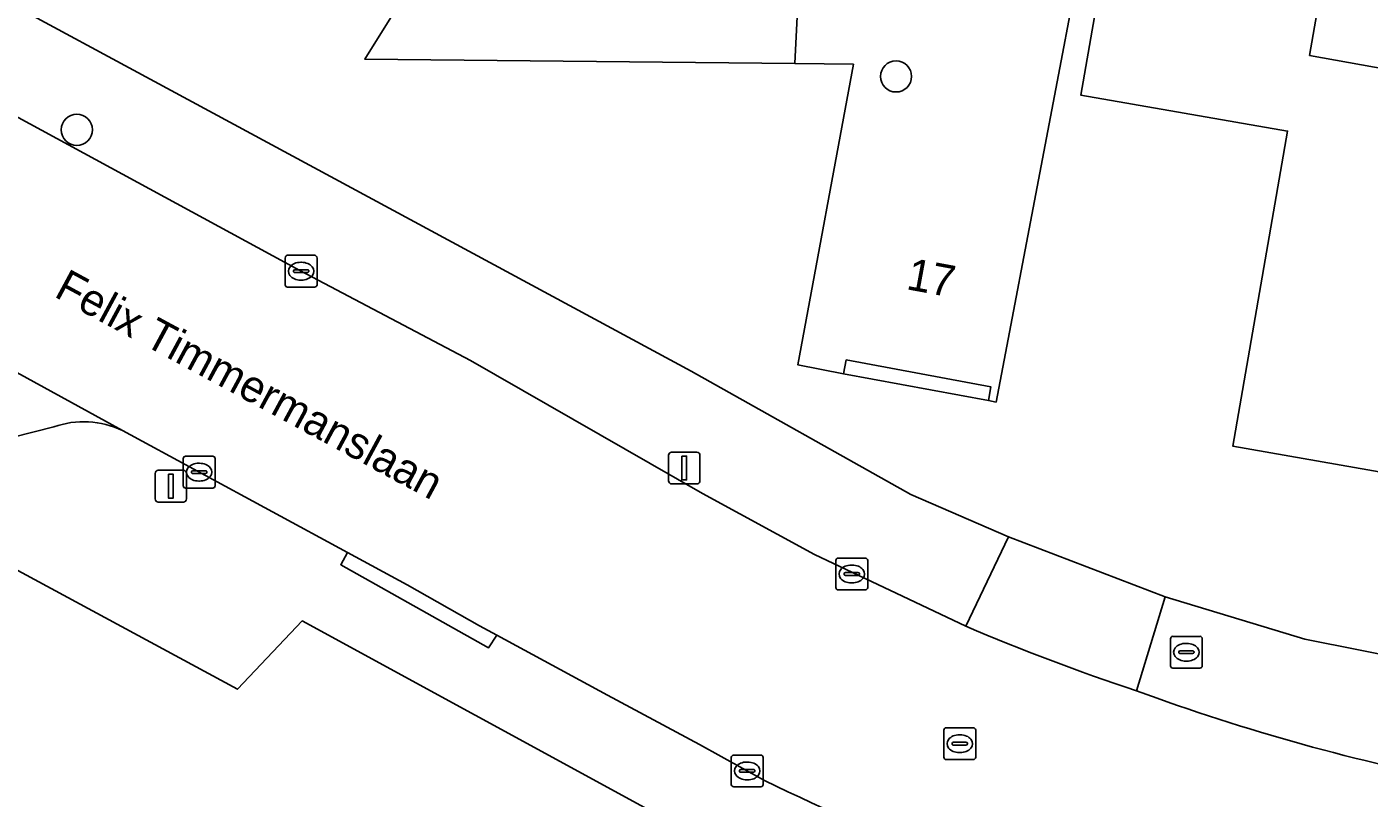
# Model space of a CAD drawing. Extents: x 161258 to 161838, y 380833 to 381727.
# Drawn here: x 161655.94 to 161698.14, y 381051.29 to 381075.53 of the extents above; entities that cross this region are included whole.
import ezdxf

# ---------------------------------------------------------------- set-up
doc = ezdxf.new("R2010")
doc.units = 0
for name, color, linetype in [('IMGEO_Boom', 7, 'Continuous'), ('IMGEO_Brandkraan', 7, 'Continuous'), ('IMGEO_Erf', 7, 'Continuous'), ('IMGEO_Kolk', 7, 'Continuous'), ('IMGEO_Lichtmast', 7, 'Continuous'), ('IMGEO_Muur', 7, 'Continuous'), ('IMGEO_Openbare_ruimte_label', 7, 'Continuous'), ('IMGEO_Pand', 7, 'Continuous'), ('IMGEO_Pand_nummerreeks', 7, 'Continuous'), ('IMGEO_Pand_overbouw', 7, 'Continuous'), ('IMGEO_Parkeervlak_open', 7, 'Continuous'), ('IMGEO_Rijbaan_lokaal_open', 7, 'Continuous'), ('IMGEO_Rioolput', 7, 'Continuous'), ('IMGEO_Voetpad_open', 7, 'Continuous')]:
    doc.layers.add(name, color=color, linetype=linetype)

msp = doc.modelspace()

# ---------------------------------------------------------------- linework, layer by layer
at = {"layer": 'IMGEO_Boom'}
for centre in [(161683.262, 381073.968), (161657.506, 381072.291)]:
    msp.add_circle(centre, 0.489, dxfattribs=at)
at = {"layer": 'IMGEO_Brandkraan'}
for p, q in [((161691.891, 381055.445), (161691.891, 381056.297)), ((161691.966, 381056.371), (161692.818, 381056.371)), ((161692.892, 381056.297), (161692.892, 381055.445)), ((161692.15, 381055.865), (161692.15, 381055.877)), ((161692.193, 381055.914), (161692.591, 381055.914)), ((161692.379, 381056.151), (161692.404, 381056.151)), ((161692.634, 381055.877), (161692.634, 381055.865)), ((161692.588, 381055.828), (161692.19, 381055.828)), ((161692.402, 381055.591), (161692.377, 381055.591)), ((161692.818, 381055.371), (161691.966, 381055.371))]:
    msp.add_line(p, q, dxfattribs=at)
for points in [[(161691.891, 381055.445), (161691.891, 381056.297)], [(161691.966, 381056.371), (161692.818, 381056.371)], [(161692.892, 381056.297), (161692.892, 381055.445)], [(161692.818, 381055.371), (161691.966, 381055.371)]]:
    msp.add_lwpolyline(points, dxfattribs=at)
for centre, radius, start, end in [((161691.968, 381056.295), 0.0765, 91.552, 178.448), ((161691.968, 381056.295), 0.0765, 91.552, 178.448), ((161692.816, 381056.295), 0.0765, 1.552, 88.448), ((161692.816, 381056.295), 0.0765, 1.552, 88.448), ((161692.19, 381055.874), 0.0403, 85.8775, 175.7526), ((161692.595, 381055.876), 0.0386, 1.7309, 96.639), ((161692.187, 381055.864), 0.0366, 178.938, 274.7102), ((161692.591, 381055.871), 0.043, 264.8664, 352.4533), ((161691.968, 381055.447), 0.0765, 181.552, 268.448), ((161691.968, 381055.447), 0.0765, 181.552, 268.448), ((161692.816, 381055.447), 0.0765, 271.552, 358.448), ((161692.816, 381055.447), 0.0765, 271.552, 358.448)]:
    msp.add_arc(centre, radius, start, end, dxfattribs=at)
for centre, major_axis, ratio, start_param, end_param in [((161692.378, 381055.871), (-0.387, 0.002), 0.722429, 4.712389, 7.853982), ((161692.403, 381055.871), (-0.39, 0.002), 0.717154, 1.570796, 4.712389)]:
    msp.add_ellipse(centre, major_axis=major_axis, ratio=ratio, start_param=start_param, end_param=end_param, dxfattribs=at)
at = {"layer": 'IMGEO_Erf'}
for points in [[(161599.292, 381107.15), (161603.367, 381104.463), (161608.252, 381101.703), (161676.825, 381064.703), (161683.729, 381060.833), (161686.794, 381059.495), (161691.724, 381057.608), (161696.114, 381056.287), (161709.767, 381053.57)], [(161689.325, 381079.031), (161686.406, 381063.731), (161686.171, 381063.778), (161686.239, 381064.217), (161681.697, 381065.06), (161681.611, 381064.618), (161680.177, 381064.899), (161681.925, 381074.353), (161680.083, 381074.372), (161680.401, 381080.903)], [(161696.768, 381077.515), (161696.265, 381074.626), (161709.453, 381072.261), (161709.255, 381071.129), (161707.307, 381059.995), (161699.889, 381061.293), (161693.85, 381062.349), (161695.574, 381072.251), (161689.072, 381073.384), (161689.93, 381078.31)], [(161675.471, 381050.931), (161664.588, 381056.855), (161662.556, 381054.709), (161631.294, 381071.59)]]:
    msp.add_lwpolyline(points, dxfattribs=at)
at = {"layer": 'IMGEO_Kolk'}
for p, q in [((161664.057, 381067.42), (161664.057, 381068.272)), ((161664.132, 381068.346), (161664.984, 381068.346)), ((161664.545, 381068.126), (161664.57, 381068.126)), ((161665.058, 381068.272), (161665.058, 381067.42)), ((161664.316, 381067.84), (161664.316, 381067.852)), ((161664.754, 381067.803), (161664.356, 381067.803)), ((161664.359, 381067.889), (161664.757, 381067.889)), ((161664.8, 381067.852), (161664.8, 381067.84)), ((161664.984, 381067.346), (161664.132, 381067.346)), ((161664.568, 381067.566), (161664.543, 381067.566)), ((161660.852, 381061.105), (161660.852, 381061.957)), ((161660.927, 381062.031), (161661.779, 381062.031)), ((161661.34, 381061.811), (161661.365, 381061.811)), ((161661.853, 381061.957), (161661.853, 381061.105)), ((161661.111, 381061.525), (161661.111, 381061.537)), ((161661.549, 381061.488), (161661.151, 381061.488)), ((161661.154, 381061.574), (161661.552, 381061.574)), ((161661.595, 381061.537), (161661.595, 381061.525)), ((161661.779, 381061.031), (161660.927, 381061.031)), ((161661.363, 381061.251), (161661.338, 381061.251)), ((161681.445, 381058.83), (161682.297, 381058.83)), ((161681.37, 381057.904), (161681.37, 381058.756)), ((161681.858, 381058.61), (161681.883, 381058.61)), ((161682.371, 381058.756), (161682.371, 381057.904)), ((161681.629, 381058.324), (161681.629, 381058.336)), ((161682.067, 381058.287), (161681.669, 381058.287)), ((161681.672, 381058.373), (161682.07, 381058.373)), ((161681.881, 381058.05), (161681.856, 381058.05)), ((161682.113, 381058.336), (161682.113, 381058.324)), ((161682.297, 381057.83), (161681.445, 381057.83)), ((161678.083, 381051.715), (161678.083, 381052.567)), ((161678.158, 381052.641), (161679.01, 381052.641)), ((161679.084, 381052.567), (161679.084, 381051.715)), ((161678.342, 381052.135), (161678.342, 381052.147)), ((161678.78, 381052.098), (161678.382, 381052.098)), ((161678.385, 381052.184), (161678.783, 381052.184)), ((161678.571, 381052.421), (161678.596, 381052.421)), ((161678.826, 381052.147), (161678.826, 381052.135)), ((161678.594, 381051.861), (161678.569, 381051.861)), ((161679.01, 381051.641), (161678.158, 381051.641))]:
    msp.add_line(p, q, dxfattribs=at)
for points in [[(161664.057, 381067.42), (161664.057, 381068.272)], [(161664.132, 381068.346), (161664.984, 381068.346)], [(161665.058, 381068.272), (161665.058, 381067.42)], [(161664.984, 381067.346), (161664.132, 381067.346)], [(161660.852, 381061.105), (161660.852, 381061.957)], [(161660.927, 381062.031), (161661.779, 381062.031)], [(161661.853, 381061.957), (161661.853, 381061.105)], [(161661.779, 381061.031), (161660.927, 381061.031)], [(161681.445, 381058.83), (161682.297, 381058.83)], [(161681.37, 381057.904), (161681.37, 381058.756)], [(161682.371, 381058.756), (161682.371, 381057.904)], [(161682.297, 381057.83), (161681.445, 381057.83)], [(161678.083, 381051.715), (161678.083, 381052.567)], [(161678.158, 381052.641), (161679.01, 381052.641)], [(161679.084, 381052.567), (161679.084, 381051.715)], [(161679.01, 381051.641), (161678.158, 381051.641)]]:
    msp.add_lwpolyline(points, dxfattribs=at)
for centre, radius, start, end in [((161664.134, 381068.27), 0.0765, 91.552, 178.448), ((161664.134, 381068.27), 0.0765, 91.552, 178.448), ((161664.982, 381068.27), 0.0765, 1.552, 88.448), ((161664.982, 381068.27), 0.0765, 1.552, 88.448), ((161664.356, 381067.849), 0.0403, 85.8775, 175.7526), ((161664.353, 381067.839), 0.0366, 178.938, 274.7102), ((161664.757, 381067.846), 0.043, 264.8664, 352.4533), ((161664.761, 381067.851), 0.0386, 1.7309, 96.639), ((161664.134, 381067.422), 0.0765, 181.552, 268.448), ((161664.134, 381067.422), 0.0765, 181.552, 268.448), ((161664.982, 381067.422), 0.0765, 271.552, 358.448), ((161664.982, 381067.422), 0.0765, 271.552, 358.448), ((161660.929, 381061.955), 0.0765, 91.552, 178.448), ((161660.929, 381061.955), 0.0765, 91.552, 178.448), ((161661.777, 381061.955), 0.0765, 1.552, 88.448), ((161661.777, 381061.955), 0.0765, 1.552, 88.448), ((161661.151, 381061.534), 0.0403, 85.8775, 175.7526), ((161661.148, 381061.524), 0.0366, 178.938, 274.7102), ((161661.552, 381061.531), 0.043, 264.8664, 352.4533), ((161661.556, 381061.536), 0.0386, 1.7309, 96.639), ((161660.929, 381061.107), 0.0765, 181.552, 268.448), ((161660.929, 381061.107), 0.0765, 181.552, 268.448), ((161661.777, 381061.107), 0.0765, 271.552, 358.448), ((161661.777, 381061.107), 0.0765, 271.552, 358.448), ((161681.447, 381058.754), 0.0765, 91.552, 178.448), ((161681.447, 381058.754), 0.0765, 91.552, 178.448), ((161682.295, 381058.754), 0.0765, 1.552, 88.448), ((161682.295, 381058.754), 0.0765, 1.552, 88.448), ((161681.669, 381058.333), 0.0403, 85.8775, 175.7526), ((161681.666, 381058.323), 0.0366, 178.938, 274.7102), ((161682.07, 381058.33), 0.043, 264.8664, 352.4533), ((161682.074, 381058.335), 0.0386, 1.7309, 96.639), ((161681.447, 381057.906), 0.0765, 181.552, 268.448), ((161681.447, 381057.906), 0.0765, 181.552, 268.448), ((161682.295, 381057.906), 0.0765, 271.552, 358.448), ((161682.295, 381057.906), 0.0765, 271.552, 358.448), ((161678.16, 381052.565), 0.0765, 91.552, 178.448), ((161678.16, 381052.565), 0.0765, 91.552, 178.448), ((161679.008, 381052.565), 0.0765, 1.552, 88.448), ((161679.008, 381052.565), 0.0765, 1.552, 88.448), ((161678.382, 381052.144), 0.0403, 85.8775, 175.7526), ((161678.379, 381052.134), 0.0366, 178.938, 274.7102), ((161678.783, 381052.141), 0.043, 264.8664, 352.4533), ((161678.787, 381052.146), 0.0386, 1.7309, 96.639), ((161678.16, 381051.717), 0.0765, 181.552, 268.448), ((161678.16, 381051.717), 0.0765, 181.552, 268.448), ((161679.008, 381051.717), 0.0765, 271.552, 358.448), ((161679.008, 381051.717), 0.0765, 271.552, 358.448)]:
    msp.add_arc(centre, radius, start, end, dxfattribs=at)
for centre, major_axis, ratio, start_param, end_param in [((161664.544, 381067.846), (-0.387, 0.002), 0.722429, 4.712389, 7.853982), ((161664.569, 381067.846), (-0.39, 0.002), 0.717154, 1.570796, 4.712389), ((161661.339, 381061.531), (-0.387, 0.002), 0.722429, 4.712389, 7.853982), ((161661.364, 381061.531), (-0.39, 0.002), 0.717154, 1.570796, 4.712389), ((161681.857, 381058.33), (-0.387, 0.002), 0.722429, 4.712389, 7.853982), ((161681.882, 381058.33), (-0.39, 0.002), 0.717154, 1.570796, 4.712389), ((161678.57, 381052.141), (-0.387, 0.002), 0.722429, 4.712389, 7.853982), ((161678.595, 381052.141), (-0.39, 0.002), 0.717154, 1.570796, 4.712389)]:
    msp.add_ellipse(centre, major_axis=major_axis, ratio=ratio, start_param=start_param, end_param=end_param, dxfattribs=at)
at = {"layer": 'IMGEO_Lichtmast'}
for p, q in [((161676.108, 381061.261), (161676.108, 381062.061)), ((161676.108, 381062.061), (161676.108, 381061.261)), ((161676.208, 381062.161), (161676.998, 381062.161)), ((161676.998, 381062.161), (161676.208, 381062.161)), ((161677.098, 381062.061), (161677.098, 381061.261)), ((161677.098, 381061.261), (161677.098, 381062.061)), ((161659.967, 381060.689), (161659.967, 381061.489)), ((161659.967, 381061.489), (161659.967, 381060.689)), ((161660.067, 381061.589), (161660.857, 381061.589)), ((161660.857, 381061.589), (161660.067, 381061.589)), ((161660.957, 381061.489), (161660.957, 381060.689)), ((161660.957, 381060.689), (161660.957, 381061.489)), ((161676.998, 381061.161), (161676.208, 381061.161)), ((161676.208, 381061.161), (161676.998, 381061.161)), ((161660.857, 381060.589), (161660.067, 381060.589)), ((161660.067, 381060.589), (161660.857, 381060.589))]:
    msp.add_line(p, q, dxfattribs=at)
for points in [[(161676.528, 381062.036), (161676.678, 381062.036), (161676.678, 381061.286), (161676.528, 381061.286), (161676.528, 381062.036)], [(161660.387, 381061.464), (161660.537, 381061.464), (161660.537, 381060.714), (161660.387, 381060.714), (161660.387, 381061.464)]]:
    msp.add_lwpolyline(points, dxfattribs=at)
for centre, start, end in [((161676.208, 381062.061), 90, 180), ((161676.208, 381062.061), 90, 180), ((161676.998, 381062.061), 0, 90), ((161676.998, 381062.061), 360, 90), ((161660.067, 381061.489), 90, 180), ((161660.067, 381061.489), 90, 180), ((161660.857, 381061.489), 0, 90), ((161660.857, 381061.489), 360, 90), ((161676.208, 381061.261), 180, 270), ((161676.208, 381061.261), 180, 270), ((161676.998, 381061.261), 270, 0), ((161676.998, 381061.261), 270, 0), ((161660.067, 381060.689), 180, 270), ((161660.067, 381060.689), 180, 270), ((161660.857, 381060.689), 270, 0), ((161660.857, 381060.689), 270, 0)]:
    msp.add_arc(centre, 0.1, start, end, dxfattribs=at)
at = {"layer": 'IMGEO_Muur'}
msp.add_lwpolyline([(161680.083, 381074.372), (161666.561, 381074.513), (161667.643, 381076.236)], dxfattribs=at)
at = {"layer": 'IMGEO_Pand'}
for points in [[(161689.325, 381079.031), (161689.346, 381079.153), (161680.401, 381080.903), (161680.083, 381074.372), (161681.925, 381074.353), (161680.177, 381064.899), (161681.611, 381064.618), (161681.697, 381065.06), (161686.239, 381064.217), (161686.171, 381063.778), (161686.406, 381063.731)], [(161709.255, 381071.129), (161709.453, 381072.261), (161696.265, 381074.626), (161696.768, 381077.515), (161696.81, 381077.754), (161690.034, 381078.905), (161689.93, 381078.31), (161689.072, 381073.384), (161695.574, 381072.251), (161693.85, 381062.349), (161699.889, 381061.293), (161707.307, 381059.995)]]:
    msp.add_lwpolyline(points, close=True, dxfattribs=at)
at = {"layer": 'IMGEO_Pand_overbouw'}
msp.add_lwpolyline([(161686.171, 381063.778), (161686.239, 381064.217), (161681.697, 381065.06), (161681.611, 381064.618)], close=True, dxfattribs=at)
at = {"layer": 'IMGEO_Parkeervlak_open'}
for points in [[(161658.944, 381062.836), (161645.436, 381070.252), (161638.895, 381073.701), (161634.807, 381075.723), (161632.244, 381076.986), (161631.678, 381077.263), (161632.464, 381076.312), (161632.865, 381074.999)], [(161655.5, 381062.629), (161656.781, 381062.954)]]:
    msp.add_lwpolyline(points, dxfattribs=at)
msp.add_arc((161657.721, 381060.295), 2.82, 64.2897, 109.4651, dxfattribs=at)
at = {"layer": 'IMGEO_Rijbaan_lokaal_open'}
msp.add_lwpolyline([(161685.459, 381056.689), (161680.698, 381058.941), (161677.177, 381060.856), (161669.88, 381065.045), (161664.516, 381067.867), (161654.689, 381073.206), (161651.628, 381074.813), (161638.009, 381081.966), (161635.58, 381083.294), (161632.244, 381076.986), (161634.807, 381075.723), (161638.895, 381073.701), (161645.436, 381070.252), (161658.944, 381062.836), (161666.013, 381059.008), (161667.897, 381057.988), (161670.17, 381056.699), (161670.707, 381056.408), (161674.187, 381054.522), (161677.079, 381052.97), (161679.132, 381051.841)], dxfattribs=at)
for centre, radius, start, end in [((161712.678, 381120.499), 69.373, 246.89865, 251.63862), ((161713.726, 381116.881), 66.304, 249.79383, 259.24998), ((161713.742, 381122.865), 79.008, 244.02026, 253.45591)]:
    msp.add_arc(centre, radius, start, end, dxfattribs=at)
at = {"layer": 'IMGEO_Rioolput'}
for p, q in [((161684.766, 381052.571), (161684.766, 381053.423)), ((161684.841, 381053.497), (161685.693, 381053.497)), ((161685.767, 381053.423), (161685.767, 381052.571)), ((161685.025, 381052.991), (161685.025, 381053.003)), ((161685.463, 381052.954), (161685.065, 381052.954)), ((161685.068, 381053.04), (161685.466, 381053.04)), ((161685.254, 381053.277), (161685.279, 381053.277)), ((161685.509, 381053.003), (161685.509, 381052.991)), ((161685.693, 381052.497), (161684.841, 381052.497)), ((161685.277, 381052.717), (161685.252, 381052.717))]:
    msp.add_line(p, q, dxfattribs=at)
for points in [[(161684.766, 381052.571), (161684.766, 381053.423)], [(161684.841, 381053.497), (161685.693, 381053.497)], [(161685.767, 381053.423), (161685.767, 381052.571)], [(161685.693, 381052.497), (161684.841, 381052.497)]]:
    msp.add_lwpolyline(points, dxfattribs=at)
for centre, radius, start, end in [((161684.843, 381053.421), 0.0765, 91.552, 178.448), ((161684.843, 381053.421), 0.0765, 91.552, 178.448), ((161685.691, 381053.421), 0.0765, 1.552, 88.448), ((161685.691, 381053.421), 0.0765, 1.552, 88.448), ((161685.065, 381053), 0.0403, 85.8775, 175.7526), ((161685.062, 381052.99), 0.0366, 178.938, 274.7102), ((161685.466, 381052.997), 0.043, 264.8664, 352.4533), ((161685.47, 381053.002), 0.0386, 1.7309, 96.639), ((161684.843, 381052.573), 0.0765, 181.552, 268.448), ((161684.843, 381052.573), 0.0765, 181.552, 268.448), ((161685.691, 381052.573), 0.0765, 271.552, 358.448), ((161685.691, 381052.573), 0.0765, 271.552, 358.448)]:
    msp.add_arc(centre, radius, start, end, dxfattribs=at)
for centre, major_axis, ratio, start_param, end_param in [((161685.253, 381052.997), (-0.387, 0.002), 0.722429, 4.712389, 7.853982), ((161685.278, 381052.997), (-0.39, 0.002), 0.717154, 1.570796, 4.712389)]:
    msp.add_ellipse(centre, major_axis=major_axis, ratio=ratio, start_param=start_param, end_param=end_param, dxfattribs=at)
at = {"layer": 'IMGEO_Voetpad_open'}
for points in [[(161598.405, 381103.885), (161602.607, 381101.294), (161602.851, 381101.158), (161607.838, 381098.385), (161610.746, 381096.768), (161611.018, 381096.621), (161623.338, 381089.989), (161635.58, 381083.294), (161638.009, 381081.966), (161651.628, 381074.813), (161654.689, 381073.206), (161664.516, 381067.867), (161669.88, 381065.045), (161677.177, 381060.856), (161680.698, 381058.941), (161685.459, 381056.689), (161686.794, 381059.495), (161683.729, 381060.833), (161676.825, 381064.703), (161608.252, 381101.703)], [(161631.294, 381071.59), (161662.556, 381054.709), (161664.588, 381056.855), (161675.471, 381050.931), (161682.316, 381047.794), (161684.449, 381046.924), (161688.26, 381045.583), (161691.047, 381044.602), (161693.931, 381043.708), (161696.121, 381043.204), (161710.784, 381040.897), (161712.11, 381042.229)], [(161656.781, 381062.954), (161655.5, 381062.629)], [(161665.804, 381058.621), (161666.013, 381059.008), (161658.944, 381062.836)], [(161691.724, 381057.608), (161686.794, 381059.495), (161685.459, 381056.689)], [(161679.132, 381051.841), (161677.079, 381052.97), (161674.187, 381054.522), (161670.707, 381056.408), (161670.449, 381056.006), (161665.804, 381058.621)], [(161709.767, 381053.57), (161696.114, 381056.287), (161691.724, 381057.608), (161690.825, 381054.658)], [(161690.825, 381054.658), (161691.724, 381057.608)]]:
    msp.add_lwpolyline(points, dxfattribs=at)
msp.add_lwpolyline([(161670.707, 381056.408), (161670.17, 381056.699), (161667.897, 381057.988), (161666.013, 381059.008), (161665.804, 381058.621), (161670.449, 381056.006)], close=True, dxfattribs=at)
for centre, radius, start, end in [((161657.721, 381060.295), 2.82, 64.2897, 109.4651), ((161712.678, 381120.499), 69.373, 246.89865, 251.63862), ((161713.726, 381116.881), 66.304, 249.79383, 259.24998), ((161713.742, 381122.865), 79.008, 244.02026, 253.45591)]:
    msp.add_arc(centre, radius, start, end, dxfattribs=at)

# ---------------------------------------------------------------- texts
at = {"layer": 'IMGEO_Openbare_ruimte_label'}
msp.add_text('Felix Timmermanslaan', height=1, rotation=331.641, dxfattribs=at).set_placement((161656.756, 381067.066))
at = {"layer": 'IMGEO_Pand_nummerreeks'}
msp.add_text('17', height=1, rotation=349.5301, dxfattribs=at).set_placement((161683.553, 381067.286))

doc.saveas('drawing.dxf')
